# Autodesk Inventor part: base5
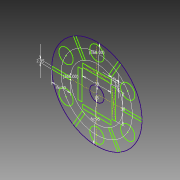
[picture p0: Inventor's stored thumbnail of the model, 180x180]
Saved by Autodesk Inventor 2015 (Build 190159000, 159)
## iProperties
Created: 2017-04
Part Number: base5
Material: Generic
Document SubType Name: Modeling
Designer: mcalderon
Density: 1 g/cm^3
Appearance: Default
Author: mcalderon
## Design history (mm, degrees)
sketch "Sketch1"
  geometry: L1 (27.536, 1.807)-(47.466, 1.807); L2 (47.486, -1.143)-(27.486, -1.143); L3 (27.486, -1.143)-(27.536, 1.807); L4 (12.204, 24.751)-(22.168, 42.01); L5 (24.733, 40.553)-(14.733, 23.232); L6 (14.733, 23.232)-(12.204, 24.751); L7 (-15.333, 22.944)-(-25.298, 40.203); L8 (-22.753, 41.696)-(-12.753, 24.375); L9 (-12.753, 24.375)-(-15.333, 22.944); L10 (-27.536, -1.807)-(-47.466, -1.807); L11 (-47.486, 1.143)-(-27.486, 1.143); L12 (-27.486, 1.143)-(-27.536, -1.807); L13 (-12.204, -24.751)-(-22.168, -42.01); L14 (-24.733, -40.553)-(-14.733, -23.232); L15 (-14.733, -23.232)-(-12.204, -24.751); L16 (15.333, -22.944)-(25.298, -40.203); L17 (22.753, -41.696)-(12.753, -24.375); L18 (12.753, -24.375)-(15.333, -22.944); L19 (0, 47.5)-(0, -47.5); L20 (-15.753, -15)-(-19.753, -15); L21 (-19.753, -15)-(-19.753, 15); L22 (-19.753, 15)-(-15.753, 15); L23 (-15.753, 15)-(-15.753, -15); L24 (-15.753, -15)-(-19.753, 15); L25 (-19.753, -15)-(-15.753, 15); L26 (15.753, 15)-(15.753, -15); L27 (19.753, 15)-(15.753, 15); L28 (19.753, -15)-(19.753, 15); L29 (15.753, -15)-(19.753, -15); L30 (15, 20.739)-(-15, 20.739); L31 (-15, 20.739)-(-15, 16.739); L32 (-15, 16.739)-(15, 16.739); L33 (15, 16.739)-(15, 20.739); L34 (15, 20.739)-(-15, 16.739); L35 (-15, 20.739)-(15, 16.739); L36 (-27.536, 0)-(27.506, 0); L37 (15, -16.739)-(15, -20.739); L38 (15, -20.739)-(-15, -20.739); L39 (-15, -16.739)-(15, -16.739); L40 (-15, -20.739)-(-15, -16.739); C1 r 7.5 at (0, 0); C2 r 7.5 at (0, 37.478); C3 r 7.5 at (-32.457, 18.739); C4 r 7.5 at (-32.457, -18.739); C5 r 7.5 at (0, -37.478); C6 r 7.5 at (32.457, -18.739); C7 r 7.5 at (32.457, 18.739); A1 r 47.5 centre (0, 0) between (47.5, 0) and (47.466, 1.807); 3 further points
  constraints: 80 end point, 8 centre point, 8 symmetric about line, 5 parallel, 5 point on circle, 4 horizontal, 4 midpoint, 3 point on line, 2 coincident, 2 perpendicular, 56 other
  dimensions: "d0" = 15 diameter of C1; "d1" = 95 diameter of A1 (= d0 + 2 x space); "d2" = 20 distance of L2.start L2.end (= 0.5 x space); "d3" = 2.95 distance of L1.end L2.start; "d6" = 360 deg dimension on point (0, 0) L1.start (derived); "d10" = 360 deg dimension on point (0, 0) C2.centre (derived); "d12" = 4 distance of L21.end L22.end; "d13" = 30 distance of L20.end L21.end; "d14" = 30 distance of L32.end L31.end; "d15" = 4 distance of L31.end L30.end
